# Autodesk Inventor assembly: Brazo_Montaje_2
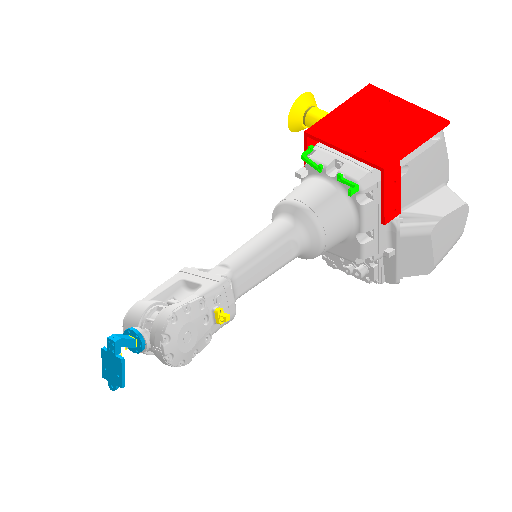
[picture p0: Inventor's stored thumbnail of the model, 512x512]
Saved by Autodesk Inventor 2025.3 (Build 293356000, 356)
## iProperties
Created: 2014-11
Part Number: Brazo_Montaje_2
Description: STEP AP203
Document SubType Name: Assembly
Designer: Dell
Sending System: SolidWorks 2012
Preprocessor: SwSTEP 2.0
Title: IRB 2600 12-1,85.STEP
Author: Jaanus
Revision Number: ANY
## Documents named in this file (11)
- C:\Users\Dell\Downloads\Tesis 2.0\CAD Final\Brazo_Montaje_2.iam
- C:\Users\Dell\Downloads\IRB 2600 12-1,85\IRB 2600 12-1,85\Link3L.ipt
- C:\Users\Dell\Downloads\IRB 2600 12-1,85\IRB 2600 12-1,85\Link4L_02.ipt
- C:\Users\Dell\Downloads\IRB 2600 12-1,85\IRB 2600 12-1,85\Link5L_02.ipt
- C:\Users\Dell\Downloads\IRB 2600 12-1,85\IRB 2600 12-1,85\Link6L.ipt
- C:\Users\Dell\Downloads\Tesis 2.0\CAD Final\Acople_Cable.ipt
- C:\Users\Dell\Downloads\Tesis 2.0\CAD Final\Acople_PLA.ipt
- C:\Users\Dell\Downloads\Tesis 2.0\CAD Final\Tapa_Carrete.ipt
- C:\Users\Dell\Downloads\Tesis 2.0\Pieza Final Arduino_2.ipt
- C:\Users\Dell\Downloads\Tesis 2.0\CAD Final\Acople_Cable_Largo.ipt
- C:\Users\Dell\Downloads\Tesis 2.0\Pieza_FINAL_EXTRUSOR.iam
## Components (11 placed, 10 different names)
1. Link3L_4 — Insertar:3, Insertar:4, Insertar:5, Insertar:8, Insertar:9
2. Link4L_02_5 — Insertar:1, Insertar:2
3. Link5L_02_6
4. Link6L_11 — Insertar:10
5. Acople_Cable:1 — Insertar:1, Insertar:2
6. Acople_PLA:1 — Insertar:6, Insertar:7
7. Tapa_Carrete:1 — Insertar:7
8. Pieza Final Arduino_2:1 — Insertar:3, Insertar:4, Insertar:5, Insertar:6
9. Acople_Cable_Largo:2 — Insertar:9
10. Acople_Cable_Largo:3 — Insertar:8
11. Pieza_FINAL_EXTRUSOR:1 [sub-assembly] — Insertar:10
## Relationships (10: Insert 10)
- Insertar:1: Link4L_02_5 ↔ Acople_Cable:1
- Insertar:2: Link4L_02_5 ↔ Acople_Cable:1
- Insertar:3: Link3L_4 ↔ Pieza Final Arduino_2:1
- Insertar:4: Link3L_4 ↔ Pieza Final Arduino_2:1
- Insertar:5: Link3L_4 ↔ Pieza Final Arduino_2:1
- Insertar:6: Acople_PLA:1 ↔ Pieza Final Arduino_2:1
- Insertar:7: Acople_PLA:1 ↔ Tapa_Carrete:1
- Insertar:8: Link3L_4 ↔ Acople_Cable_Largo:3
- Insertar:9: Link3L_4 ↔ Acople_Cable_Largo:2
- Insertar:10: Link6L_11 ↔ Pieza_FINAL_EXTRUSOR:1
